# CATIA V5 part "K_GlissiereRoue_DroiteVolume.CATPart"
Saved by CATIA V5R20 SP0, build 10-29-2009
Part number: glissiere_roue_droite_volume
Bounding box of the stored display mesh (mm): x -74.995 to 74.995, y -515 to -360, z -25 to 24.995
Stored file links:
  G:\Khaled_CFAO_2011\ST2M\ST2M_GR1\cdurantin\cdurantin\Khaled\CAD_ThinkMOTION\K_GlissiereRoue_DroiteVolume.CATPart
  C:\Documents and Settings\cdurantin\Bureau\cdurantin\caddy.CATProduct
  G:\Khaled_CFAO_2011\ST2M\ST2M_GR1\cdurantin\cdurantin\CATIA\glissiere_roue_gauche_volume.CATPart
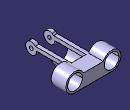
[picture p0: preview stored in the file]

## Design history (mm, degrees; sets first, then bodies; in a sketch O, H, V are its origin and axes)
Body1 (main body)
Body2
  Solid1: linked copy from another document
  Symmetry1: Reference zx-plane, ToTransfor Solid1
